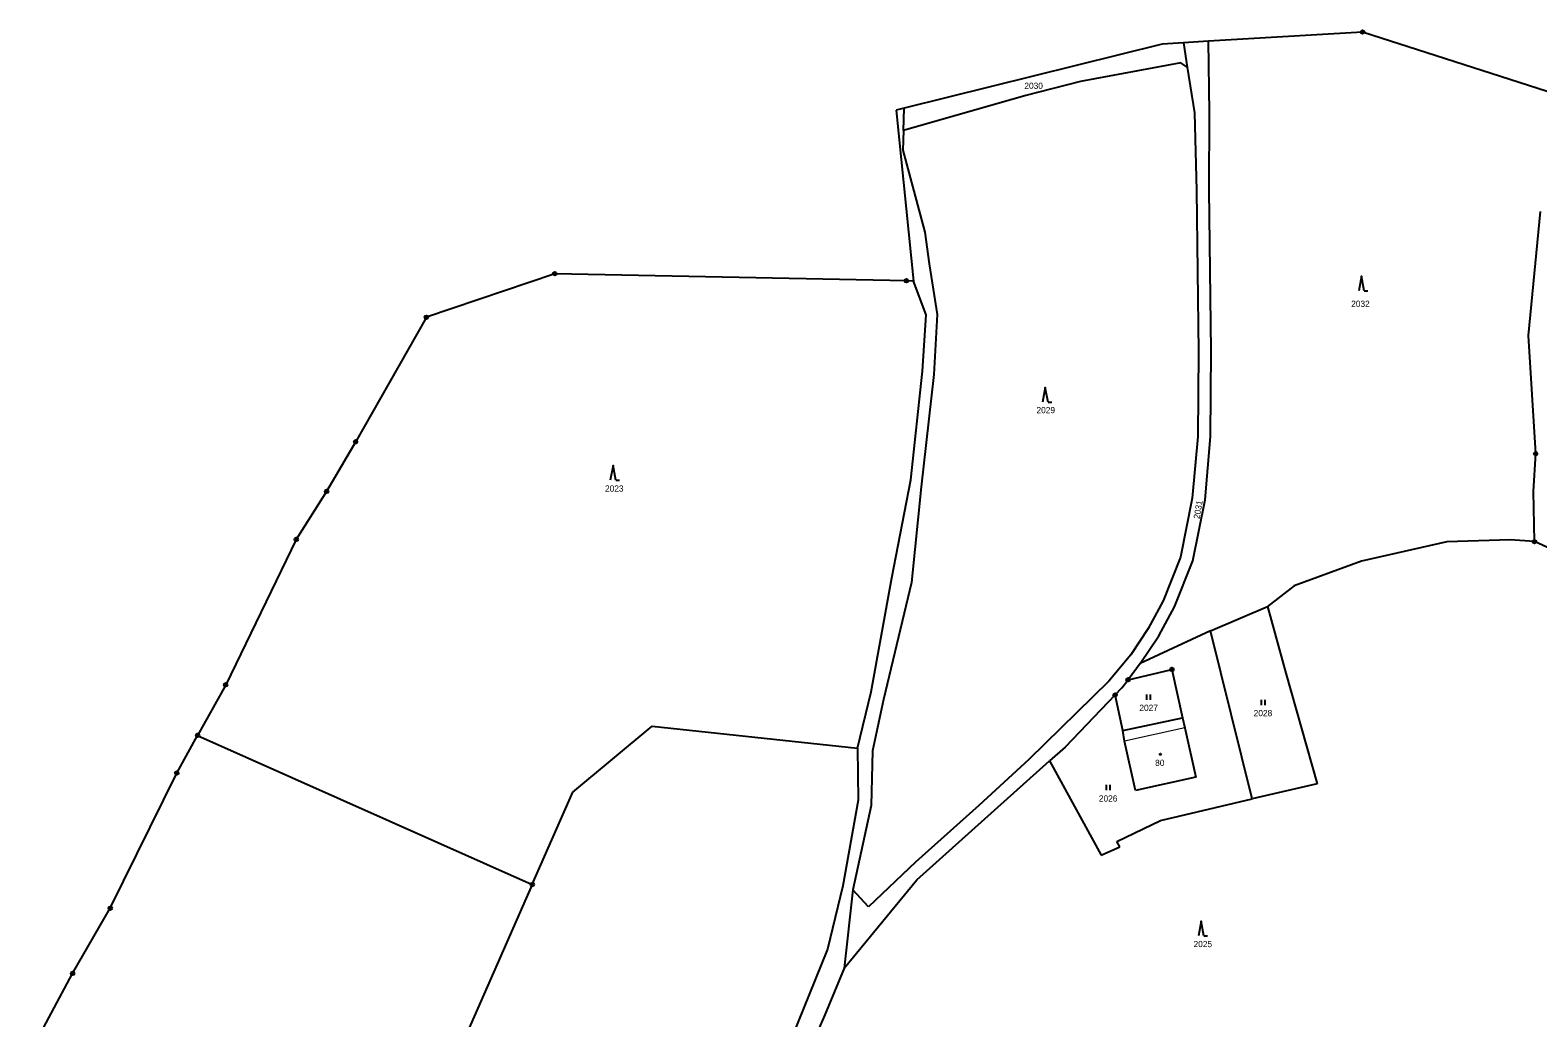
# Model space of a CAD drawing. Extents: x -601131 to -597152, y -1058536 to -1055911.
# Drawn here: x -597993.3 to -597581.6, y -1056181 to -1055911.5 of the extents above; entities that cross this region are included whole.
import ezdxf
from ezdxf.enums import TextEntityAlignment as Align

# ---------------------------------------------------------------- set-up
doc = ezdxf.new("R2010")
doc.units = 0
doc.header["$LTSCALE"] = 0.68
for name, color, linetype, lineweight in [('1', 7, 'Continuous', 25), ('3', 7, 'Continuous', 25), ('4', 7, 'Continuous', 13), ('5', 7, 'Continuous', 25), ('8', 7, 'Continuous', 25)]:
    doc.layers.add(name, color=color, linetype=linetype, lineweight=lineweight)
doc.layers.add('2', color=7, linetype='Continuous')

msp = doc.modelspace()

# ---------------------------------------------------------------- linework, layer by layer
at = {"layer": '1'}
for p, q in [((-597678.39, -1055914.93), (-597684.22, -1055915.28)), ((-597678.39, -1055914.93), (-597677.34, -1055921.62)), ((-597671.29, -1055933.95), (-597671.58, -1055914.52)), ((-597679.13, -1055920.37), (-597706.54, -1055925.49)), ((-597677.34, -1055921.62), (-597679.13, -1055920.37)), ((-597677.34, -1055921.62), (-597675.38, -1055934.05)), ((-597706.54, -1055925.49), (-597721.42, -1055929.33)), ((-597721.42, -1055929.33), (-597754.84, -1055938.83)), ((-597754.84, -1055938.83), (-597754.63, -1055932.79)), ((-597675.38, -1055934.05), (-597674.85, -1055955.23)), ((-597671.35, -1055955.07), (-597671.29, -1055933.95)), ((-597754.84, -1055938.83), (-597755.02, -1055944.21)), ((-597755.02, -1055944.21), (-597748.98, -1055966.58)), ((-597674.85, -1055955.23), (-597674.28, -1055999.28)), ((-597670.79, -1055999.02), (-597671.35, -1055955.07)), ((-597584.17, -1055994.82), (-597580.89, -1055960.93)), ((-597748.98, -1055966.58), (-597747.79, -1055975.29)), ((-597747.79, -1055975.29), (-597745.6, -1055989.09)), ((-597850.06, -1055977.94), (-597885.11, -1055989.81)), ((-597754.02, -1055979.88), (-597850.06, -1055977.94)), ((-597748.6, -1055989.17), (-597752.1, -1055979.99)), ((-597885.11, -1055989.81), (-597895.28, -1056007.68)), ((-597749.62, -1056004.54), (-597748.6, -1055989.17)), ((-597745.6, -1055989.09), (-597746.54, -1056005.41)), ((-597582.18, -1056027.05), (-597584.17, -1055994.82)), ((-597674.28, -1055999.28), (-597674.46, -1056022.37)), ((-597670.96, -1056022.37), (-597670.79, -1055999.02)), ((-597752.82, -1056034.23), (-597749.62, -1056004.54)), ((-597746.54, -1056005.41), (-597749.97, -1056036.14)), ((-597895.28, -1056007.68), (-597904.44, -1056023.78)), ((-597674.46, -1056022.37), (-597675.96, -1056039.19)), ((-597672.49, -1056039.66), (-597670.96, -1056022.37)), ((-597904.44, -1056023.78), (-597912.38, -1056037.37)), ((-597582.75, -1056037.42), (-597582.18, -1056027.05)), ((-597758.03, -1056060.98), (-597752.82, -1056034.23)), ((-597912.38, -1056037.37), (-597920.66, -1056050.47)), ((-597749.97, -1056036.14), (-597752.65, -1056062.22)), ((-597675.96, -1056039.19), (-597679.2, -1056055.31)), ((-597582.54, -1056051.07), (-597582.75, -1056037.42)), ((-597675.84, -1056056.3), (-597672.49, -1056039.66)), ((-597920.66, -1056050.47), (-597939.94, -1056090.13)), ((-597606.46, -1056051.09), (-597629.72, -1056056.4)), ((-597589.17, -1056050.58), (-597606.46, -1056051.09)), ((-597582.54, -1056051.07), (-597589.17, -1056050.58)), ((-597577.92, -1056053.14), (-597582.54, -1056051.07)), ((-597679.2, -1056055.31), (-597683.91, -1056067.19)), ((-597680.82, -1056068.83), (-597675.84, -1056056.3)), ((-597629.72, -1056056.4), (-597648.13, -1056063.17)), ((-597763.7, -1056092.06), (-597758.03, -1056060.98)), ((-597752.65, -1056062.22), (-597760.27, -1056094.16)), ((-597648.13, -1056063.17), (-597655.46, -1056068.78)), ((-597683.91, -1056067.19), (-597687.99, -1056074.81)), ((-597685.09, -1056076.77), (-597680.82, -1056068.83)), ((-597671.02, -1056075.38), (-597655.46, -1056068.78)), ((-597655.46, -1056068.78), (-597650.42, -1056086.99)), ((-597687.99, -1056074.81), (-597692.74, -1056081.96)), ((-597671.02, -1056075.38), (-597690.19, -1056084.35)), ((-597659.62, -1056121.29), (-597671.02, -1056075.38)), ((-597690.19, -1056084.35), (-597685.09, -1056076.77)), ((-597692.74, -1056081.96), (-597698.8, -1056089.15)), ((-597690.19, -1056084.35), (-597693.52, -1056088.77)), ((-597695.19, -1056090.98), (-597693.52, -1056088.77)), ((-597693.52, -1056088.77), (-597681.53, -1056085.94)), ((-597681.53, -1056085.94), (-597678.6, -1056099.18)), ((-597650.42, -1056086.99), (-597641.85, -1056117.13)), ((-597939.94, -1056090.13), (-597947.6, -1056103.94)), ((-597767.44, -1056107.44), (-597763.7, -1056092.06)), ((-597698.8, -1056089.15), (-597720.57, -1056110.53)), ((-597697.05, -1056092.91), (-597710.68, -1056107.17)), ((-597697.05, -1056092.91), (-597695.19, -1056090.98)), ((-597694.97, -1056102.64), (-597697.05, -1056092.91)), ((-597760.27, -1056094.16), (-597763.28, -1056108.18)), ((-597694.97, -1056102.64), (-597678.6, -1056099.18)), ((-597678.6, -1056099.18), (-597677.98, -1056101.88)), ((-597953.3, -1056114.21), (-597947.6, -1056103.94)), ((-597947.6, -1056103.94), (-597856.22, -1056144.64)), ((-597845.1, -1056119.41), (-597823.5, -1056101.42)), ((-597823.5, -1056101.42), (-597767.44, -1056107.44)), ((-597694.44, -1056105.54), (-597694.97, -1056102.64)), ((-597677.98, -1056101.88), (-597674.99, -1056115.32)), ((-597767.44, -1056107.44), (-597767.19, -1056121.61)), ((-597763.28, -1056108.18), (-597763.65, -1056123.11)), ((-597710.68, -1056107.17), (-597714.95, -1056110.87)), ((-597691.49, -1056118.97), (-597694.44, -1056105.54)), ((-597751.22, -1056143.32), (-597714.95, -1056110.87)), ((-597720.57, -1056110.53), (-597734.28, -1056123.04)), ((-597714.95, -1056110.87), (-597700.86, -1056136.67)), ((-597971.46, -1056151.11), (-597953.3, -1056114.21)), ((-597674.99, -1056115.32), (-597691.49, -1056118.97)), ((-597641.85, -1056117.13), (-597659.62, -1056121.29)), ((-597856.22, -1056144.64), (-597845.1, -1056119.41)), ((-597767.19, -1056121.61), (-597771.39, -1056145.02)), ((-597684.68, -1056127.15), (-597659.62, -1056121.29)), ((-597763.65, -1056123.11), (-597768.71, -1056146.09)), ((-597734.28, -1056123.04), (-597751.53, -1056138.57)), ((-597696.53, -1056132.86), (-597684.68, -1056127.15)), ((-597695.79, -1056134.32), (-597696.53, -1056132.86)), ((-597700.86, -1056136.67), (-597695.79, -1056134.32)), ((-597751.53, -1056138.57), (-597764.42, -1056150.71)), ((-597856.22, -1056144.64), (-597921.03, -1056291.77)), ((-597771.39, -1056145.02), (-597775.56, -1056162.31)), ((-597771.02, -1056167.45), (-597751.22, -1056143.32)), ((-597768.71, -1056146.09), (-597771.02, -1056167.45)), ((-597764.42, -1056150.71), (-597768.71, -1056146.09)), ((-597981.76, -1056168.89), (-597971.46, -1056151.11)), ((-597775.56, -1056162.31), (-597799.37, -1056220.98)), ((-597993.34, -1056190.5), (-597981.76, -1056168.89)), ((-597771.02, -1056167.45), (-597776.35, -1056180.2)), ((-597776.35, -1056180.2), (-597795.22, -1056223.1))]:
    msp.add_line(p, q, dxfattribs=at)
for points in [[(-597684.22, -1055915.28), (-597754.63, -1055932.79), (-597756.82, -1055933.29)], [(-597629.46, -1055911.98), (-597671.58, -1055914.52), (-597678.39, -1055914.93)], [(-597566.63, -1055932.25), (-597569.16, -1055931.43), (-597629.46, -1055911.98)], [(-597756.82, -1055933.29), (-597752.1, -1055979.99), (-597754.02, -1055979.88)]]:
    msp.add_lwpolyline(points, dxfattribs=at)
at = {"layer": '3'}
for p, q in [((-597629.01, -1055982.63), (-597628.014, -1055982.63)), ((-597715.36, -1056012.96), (-597714.364, -1056012.96)), ((-597833.4, -1056034.27), (-597832.404, -1056034.27)), ((-597688.391, -1056094.26), (-597688.391, -1056092.76)), ((-597687.39, -1056094.26), (-597687.39, -1056092.76)), ((-597657.081, -1056095.7), (-597657.081, -1056094.2)), ((-597656.08, -1056095.7), (-597656.08, -1056094.2)), ((-597699.431, -1056118.91), (-597699.431, -1056117.41)), ((-597698.43, -1056118.91), (-597698.43, -1056117.41)), ((-597672.79, -1056158.68), (-597671.794, -1056158.68))]:
    msp.add_line(p, q, dxfattribs=at)
for points in [[(-597629.01, -1055982.63), (-597629.76, -1055978.63), (-597630.51, -1055982.63)], [(-597715.36, -1056012.96), (-597716.11, -1056008.96), (-597716.86, -1056012.96)], [(-597833.4, -1056034.27), (-597834.15, -1056030.27), (-597834.9, -1056034.27)], [(-597672.79, -1056158.68), (-597673.54, -1056154.68), (-597674.29, -1056158.68)]]:
    msp.add_lwpolyline(points, dxfattribs=at)
at = {"layer": '4'}
msp.add_line((-597677.98, -1056101.88), (-597694.44, -1056105.54), dxfattribs=at)
at = {"layer": '5'}
msp.add_circle((-597684.6668, -1056109.0892), 0.175, dxfattribs=at)
at = {"layer": '8'}
for centre, radius in [((-597629.46, -1055911.9799), 0.5), ((-597629.46, -1055911.9799), 0.0303), ((-597850.06, -1055977.9399), 0.5), ((-597850.06, -1055977.9399), 0.0303), ((-597754.02, -1055979.8799), 0.5), ((-597754.02, -1055979.8799), 0.0303), ((-597885.11, -1055989.8099), 0.5), ((-597885.11, -1055989.8099), 0.0303), ((-597904.44, -1056023.7799), 0.5), ((-597904.44, -1056023.7799), 0.0303), ((-597582.18, -1056027.0499), 0.5), ((-597582.18, -1056027.0499), 0.0303), ((-597912.38, -1056037.3699), 0.5), ((-597912.38, -1056037.3699), 0.0303), ((-597920.66, -1056050.4699), 0.5), ((-597920.66, -1056050.4699), 0.0303), ((-597582.54, -1056051.0699), 0.5), ((-597582.54, -1056051.0699), 0.0303), ((-597693.52, -1056088.7699), 0.5), ((-597693.52, -1056088.7699), 0.0303), ((-597681.53, -1056085.9399), 0.5), ((-597681.53, -1056085.9399), 0.0303), ((-597939.94, -1056090.1299), 0.5), ((-597939.94, -1056090.1299), 0.0303), ((-597697.05, -1056092.9099), 0.5), ((-597697.05, -1056092.9099), 0.0303), ((-597947.6, -1056103.9399), 0.5), ((-597947.6, -1056103.9399), 0.0303), ((-597953.3, -1056114.2099), 0.5), ((-597953.3, -1056114.2099), 0.0303), ((-597856.22, -1056144.6399), 0.5), ((-597856.22, -1056144.6399), 0.0303), ((-597971.46, -1056151.1099), 0.5), ((-597971.46, -1056151.1099), 0.0303), ((-597981.76, -1056168.8899), 0.5), ((-597981.76, -1056168.8899), 0.0303)]:
    msp.add_circle(centre, radius, dxfattribs=at)

# ---------------------------------------------------------------- texts
at = {"layer": '2'}
for s, p in [('2030', (-597719.29, -1055927.502)), ('2032', (-597630.04, -1055986.992)), ('2029', (-597715.98, -1056016.012)), ('2023', (-597833.81, -1056037.422)), ('2027', (-597687.88, -1056097.262)), ('2028', (-597656.66, -1056098.702)), ('80', (-597684.849, -1056112.282)), ('2026', (-597698.94, -1056122.002)), ('2025', (-597673.09, -1056161.732))]:
    msp.add_text(s, height=1.7, dxfattribs=at).set_placement(p, align=Align.CENTER)
msp.add_text('2031', height=1.7, rotation=80, dxfattribs=at).set_placement((-597673.5429, -1056042.4766), align=Align.CENTER)

doc.saveas('drawing.dxf')
